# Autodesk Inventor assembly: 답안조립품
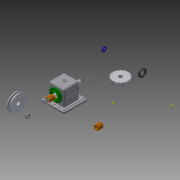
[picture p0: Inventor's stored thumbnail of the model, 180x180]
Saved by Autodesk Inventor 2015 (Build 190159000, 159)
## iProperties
Created: 2018-11
Part Number: 답안조립품
Document SubType Name: Assembly
Designer: now
Author: now
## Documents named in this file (13)
- C:\Users\now\Desktop\481108V1009\답안조립품.iam
- C:\Users\now\Desktop\481108V1009\V벨트풀리.ipt
- C:\Users\now\Desktop\481108V1009\너트 M12x1.25.ipt
- C:\Users\now\Desktop\481108V1009\베어링 6203.ipt
- C:\Users\now\Desktop\481108V1009\본체.ipt
- C:\Users\now\Desktop\481108V1009\볼트 M4.ipt
- C:\Users\now\Desktop\481108V1009\부시.ipt
- C:\Users\now\Desktop\481108V1009\스퍼기어.ipt
- C:\Users\now\Desktop\481108V1009\오일 실 26 38 8.ipt
- C:\Users\now\Desktop\481108V1009\와셔 12x24.ipt
- C:\Users\now\Desktop\481108V1009\축.ipt
- C:\Users\now\Desktop\481108V1009\커버.ipt
- C:\Users\now\Desktop\481108V1009\키 5x5x12.ipt
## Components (1 placed, 1 different names)
1. V벨트풀리:1
